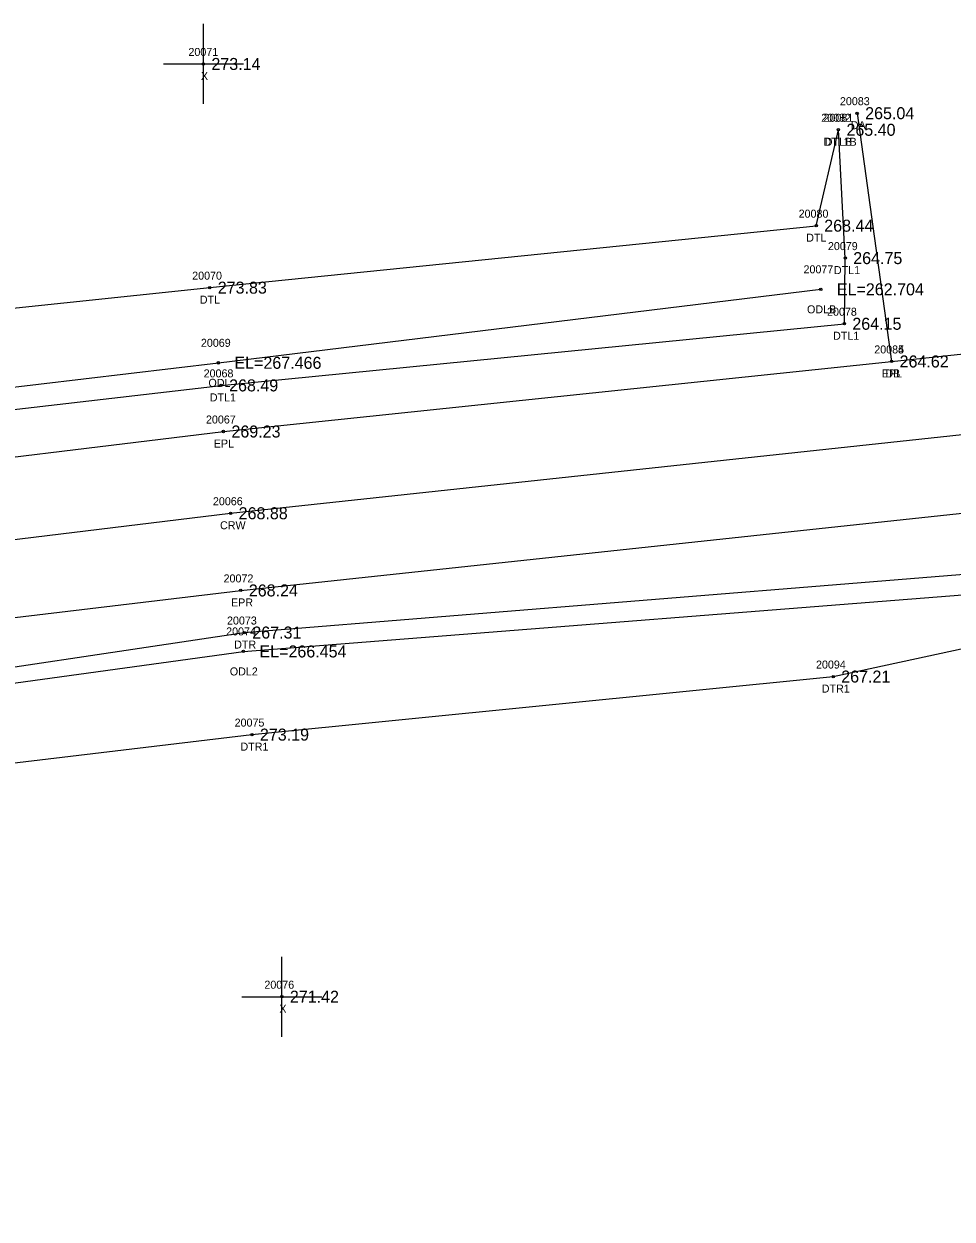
# Model space of a CAD drawing. Extents: x 2275563 to 2277161, y 1075719 to 1076412.
# Drawn here: x 2275840.8 to 2275956.7, y 1075932.2 to 1076081.5 of the extents above; entities that cross this region are included whole.
import ezdxf

# ---------------------------------------------------------------- set-up
doc = ezdxf.new("R2010")
doc.units = 0
for name, color, linetype in [('RD_DTM_BkLn1', 7, 'Continuous'), ('RD_EX_Driveway', 7, 'Continuous'), ('RD_EX_Driveway_txCode', 7, 'Continuous'), ('RD_EX_H2O', 7, 'Continuous'), ('RD_EX_H2O_txCode', 7, 'Continuous'), ('RD_EX_Misc', 7, 'Continuous'), ('RD_EX_Misc_txCode', 7, 'Continuous'), ('RD_EX_Road', 7, 'Continuous'), ('RD_EX_Road_txCode', 7, 'Continuous'), ('RD_EX_TX_Driveway_ELEV', 7, 'Continuous'), ('RD_EX_TX_H2O_ELEV', 7, 'Continuous'), ('RD_EX_TX_Misc_ELEV', 7, 'Continuous'), ('RD_EX_TX_Road_ELEV', 7, 'Continuous'), ('RD_HC_Survey_ELEV', 7, 'Continuous'), ('RD_HC_Survey_txCode', 7, 'Continuous'), ('RD_SMD_Locator', 7, 'Continuous')]:
    doc.layers.add(name, color=color, linetype=linetype)

msp = doc.modelspace()

# ---------------------------------------------------------------- linework, layer by layer
at = {"layer": 'RD_DTM_BkLn1'}
msp.add_lwpolyline([(2275581.11, 1075960.98), (2275628.56, 1075975.85), (2275676.42, 1075988.42), (2275723.3, 1075998.64), (2275773.11, 1076007.87), (2275820.75, 1076014.85), (2275866.6, 1076020.4), (2275966.91, 1076031.19), (2276055.16, 1076040.4), (2276149.88, 1076050.18), (2276235.38, 1076058.41), (2276319.71, 1076067.21)], dxfattribs=at)
at = {"layer": 'RD_EX_Driveway'}
msp.add_line((2275944.87, 1076070.37), (2275949.17, 1076039.36), dxfattribs=at)
at = {"layer": 'RD_EX_H2O'}
for points in [[(2275571.65, 1075989.72), (2275621.14, 1076003.61), (2275670.33, 1076016.76), (2275718.82, 1076028.73), (2275768.35, 1076037.39), (2275818.36, 1076043.83), (2275863.99, 1076048.58), (2275939.76, 1076056.32), (2275942.53, 1076068.3)], [(2275576.42, 1075977.43), (2275624.64, 1075992.17), (2275672.66, 1076004.86), (2275721.55, 1076015.52), (2275771.33, 1076024.61), (2275820.46, 1076031.17), (2275865.41, 1076036.37), (2275943.27, 1076044.07), (2275943.38, 1076052.27), (2275942.53, 1076068.3)], [(2275575.79, 1075980.11), (2275624.24, 1075995.2), (2275672.15, 1076008.16), (2275721.35, 1076018.05), (2275770.75, 1076027.72), (2275820.07, 1076033.88), (2275865.07, 1076039.19), (2275940.33, 1076048.37)], [(2275584.42, 1075945.55), (2275630.75, 1075959.99), (2275679.72, 1075972.8), (2275727.1, 1075983.01), (2275776.52, 1075992.46), (2275822.09, 1075998.61), (2275868.31, 1076005.5), (2275971.07, 1076013.85), (2276058.03, 1076018.84), (2276110, 1076025.4), (2276114.25, 1076022.31), (2276152.59, 1076021.64), (2276188.46, 1076022.22), (2276200.36, 1076021.35), (2276207.63, 1076015.4), (2276245.53, 1076014.24), (2276263.41, 1076017.81), (2276276.57, 1076007.97), (2276280.95, 1075989.03), (2276329.97, 1075967.39)], [(2275584.66, 1075942.4), (2275631.99, 1075956.6), (2275680.23, 1075970.55), (2275727.34, 1075980.71), (2275776.9, 1075989.93), (2275822.49, 1075996.83), (2275868.2, 1076003.14), (2275971.77, 1076011.3), (2276058.74, 1076015.62), (2276117.31, 1076020.2), (2276152.71, 1076018.31), (2276188.2, 1076020.3), (2276200.59, 1076018.25), (2276207.46, 1076011.88), (2276246.17, 1076010.02), (2276264.15, 1076012.48), (2276274.37, 1076006.56), (2276276.43, 1075986.9), (2276334.04, 1075961.68)], [(2275587.87, 1075932.23), (2275632.3, 1075945.74), (2275680.34, 1075962.3), (2275730.43, 1075971.98), (2275777.84, 1075981.49), (2275823.91, 1075987.34), (2275869.26, 1075992.75), (2275941.88, 1076000), (2275968.29, 1076005.71), (2275973.41, 1076009.09), (2276058.49, 1076013.63), (2276114.54, 1076018.47), (2276125.61, 1076012.99), (2276153.29, 1076014.06), (2276186.69, 1076017.67), (2276196.76, 1076016.05), (2276210.13, 1076008.45), (2276246.2, 1076005.42), (2276264.34, 1076010.6), (2276271.38, 1076006), (2276275.05, 1075983.37), (2276331.39, 1075956.06)]]:
    msp.add_lwpolyline(points, dxfattribs=at)
at = {"layer": 'RD_EX_Misc'}
for p, q in [((2275863.2, 1076071.52), (2275863.2, 1076081.52)), ((2275858.2, 1076076.52), (2275868.2, 1076076.52)), ((2275873, 1075955.01), (2275873, 1075965.01)), ((2275868, 1075960.01), (2275878, 1075960.01))]:
    msp.add_line(p, q, dxfattribs=at)
at = {"layer": 'RD_EX_Road'}
for points in [[(2275577.73, 1075970.55), (2275625.95, 1075985.49), (2275674.01, 1075998.04), (2275722.5, 1076008.98), (2275771.65, 1076017.82), (2275820.48, 1076025.1), (2275865.7, 1076030.61), (2275949.17, 1076039.36), (2275965.19, 1076041.07), (2276054.28, 1076050.49), (2276149.42, 1076060.39), (2276235.13, 1076068.68), (2276318.87, 1076076.96)], [(2275583.24, 1075951.04), (2275629.66, 1075965.93), (2275678.06, 1075978.68), (2275725.56, 1075989.06), (2275775.66, 1075998.23), (2275820.79, 1076005.15), (2275867.87, 1076010.76), (2275970.82, 1076021.78), (2276056.64, 1076030.61), (2276150.8, 1076040.39), (2276237.04, 1076048.76), (2276320.71, 1076057.95)]]:
    msp.add_lwpolyline(points, dxfattribs=at)
at = {"layer": 'RD_SMD_Locator'}
for centre in [(2275863.2, 1076076.52), (2275944.87, 1076070.37), (2275942.53, 1076068.3), (2275942.53, 1076068.3), (2275939.76, 1076056.32), (2275943.38, 1076052.27), (2275863.99, 1076048.58), (2275940.33, 1076048.37), (2275943.27, 1076044.07), (2275865.07, 1076039.19), (2275949.17, 1076039.36), (2275949.17, 1076039.36), (2275865.41, 1076036.37), (2275865.7, 1076030.61), (2275866.6, 1076020.4), (2275867.87, 1076010.76), (2275868.31, 1076005.5), (2275868.2, 1076003.14), (2275941.88, 1076000), (2275869.26, 1075992.75), (2275873, 1075960.01)]:
    msp.add_circle(centre, 0.15, dxfattribs=at)

# ---------------------------------------------------------------- texts
at = {"layer": 'RD_EX_Driveway_txCode'}
for s, p in [('20083', (2275942.72, 1076071.37)), ('DA', (2275944.08, 1076068.37)), ('20084', (2275947.01, 1076040.36)), ('DB', (2275948.39, 1076037.36))]:
    msp.add_text(s, height=1, dxfattribs=at).set_placement(p)
at = {"layer": 'RD_EX_H2O_txCode'}
for s, p in [('20082', (2275940.38, 1076069.3)), ('20081', (2275940.66, 1076069.3)), ('DTL1B', (2275940.65, 1076066.3)), ('DTLB', (2275940.82, 1076066.3)), ('20080', (2275937.56, 1076057.32)), ('DTL', (2275938.51, 1076054.32)), ('20079', (2275941.22, 1076053.27)), ('20077', (2275938.17, 1076050.37)), ('DTL1', (2275941.97, 1076050.27)), ('20070', (2275861.8, 1076049.58)), ('DTL', (2275862.75, 1076046.58)), ('ODLB', (2275938.61, 1076045.37)), ('20078', (2275941.11, 1076045.07)), ('20069', (2275862.89, 1076041.19)), ('DTL1', (2275941.86, 1076042.07)), ('20068', (2275863.23, 1076037.37)), ('ODL', (2275863.83, 1076036.19)), ('DTL1', (2275864, 1076034.37)), ('20073', (2275866.15, 1076006.5)), ('20074', (2275866.04, 1076005.14)), ('DTR', (2275867.04, 1076003.5)), ('20094', (2275939.73, 1076001)), ('ODL2', (2275866.5, 1076000.14)), ('DTR1', (2275940.45, 1075998)), ('20075', (2275867.1, 1075993.75)), ('DTR1', (2275867.83, 1075990.75))]:
    msp.add_text(s, height=1, dxfattribs=at).set_placement(p)
at = {"layer": 'RD_EX_Misc_txCode'}
for s, p in [('20071', (2275861.33, 1076077.52)), ('X', (2275862.89, 1076074.52)), ('20076', (2275870.82, 1075961.01)), ('X', (2275872.69, 1075958.01))]:
    msp.add_text(s, height=1, dxfattribs=at).set_placement(p)
at = {"layer": 'RD_EX_Road_txCode'}
for s, p in [('20085', (2275947.01, 1076040.36)), ('EPL', (2275947.96, 1076037.36)), ('20067', (2275863.52, 1076031.61)), ('EPL', (2275864.5, 1076028.61)), ('20072', (2275865.72, 1076011.76)), ('EPR', (2275866.65, 1076008.76))]:
    msp.add_text(s, height=1, dxfattribs=at).set_placement(p)
at = {"layer": 'RD_EX_TX_Driveway_ELEV'}
for s, p in [('265.04', (2275945.87, 1076069.62)), ('264.62', (2275950.17, 1076038.61))]:
    msp.add_text(s, height=1.5, dxfattribs=at).set_placement(p)
at = {"layer": 'RD_EX_TX_H2O_ELEV'}
for s, p in [('265.40', (2275943.53, 1076067.55)), ('265.40', (2275943.53, 1076067.55)), ('268.44', (2275940.76, 1076055.57)), ('264.75', (2275944.38, 1076051.52)), ('273.83', (2275864.99, 1076047.83)), ('EL=262.704', (2275942.33, 1076047.62)), ('264.15', (2275944.27, 1076043.32)), ('EL=267.466', (2275867.07, 1076038.44)), ('268.49', (2275866.41, 1076035.62)), ('267.31', (2275869.31, 1076004.75)), ('EL=266.454', (2275870.2, 1076002.39)), ('267.21', (2275942.88, 1075999.25)), ('273.19', (2275870.26, 1075992))]:
    msp.add_text(s, height=1.5, dxfattribs=at).set_placement(p)
at = {"layer": 'RD_EX_TX_Misc_ELEV'}
for s, p in [('273.14', (2275864.2, 1076075.77)), ('271.42', (2275874, 1075959.26))]:
    msp.add_text(s, height=1.5, dxfattribs=at).set_placement(p)
at = {"layer": 'RD_EX_TX_Road_ELEV'}
for s, p in [('264.62', (2275950.17, 1076038.61)), ('269.23', (2275866.7, 1076029.86)), ('268.24', (2275868.87, 1076010.01))]:
    msp.add_text(s, height=1.5, dxfattribs=at).set_placement(p)
at = {"layer": 'RD_HC_Survey_ELEV'}
msp.add_text('268.88', height=1.5, dxfattribs=at).set_placement((2275867.6, 1076019.65))
at = {"layer": 'RD_HC_Survey_txCode'}
for s, p in [('20066', (2275864.39, 1076021.4)), ('CRW', (2275865.28, 1076018.4))]:
    msp.add_text(s, height=1, dxfattribs=at).set_placement(p)

doc.saveas('drawing.dxf')
